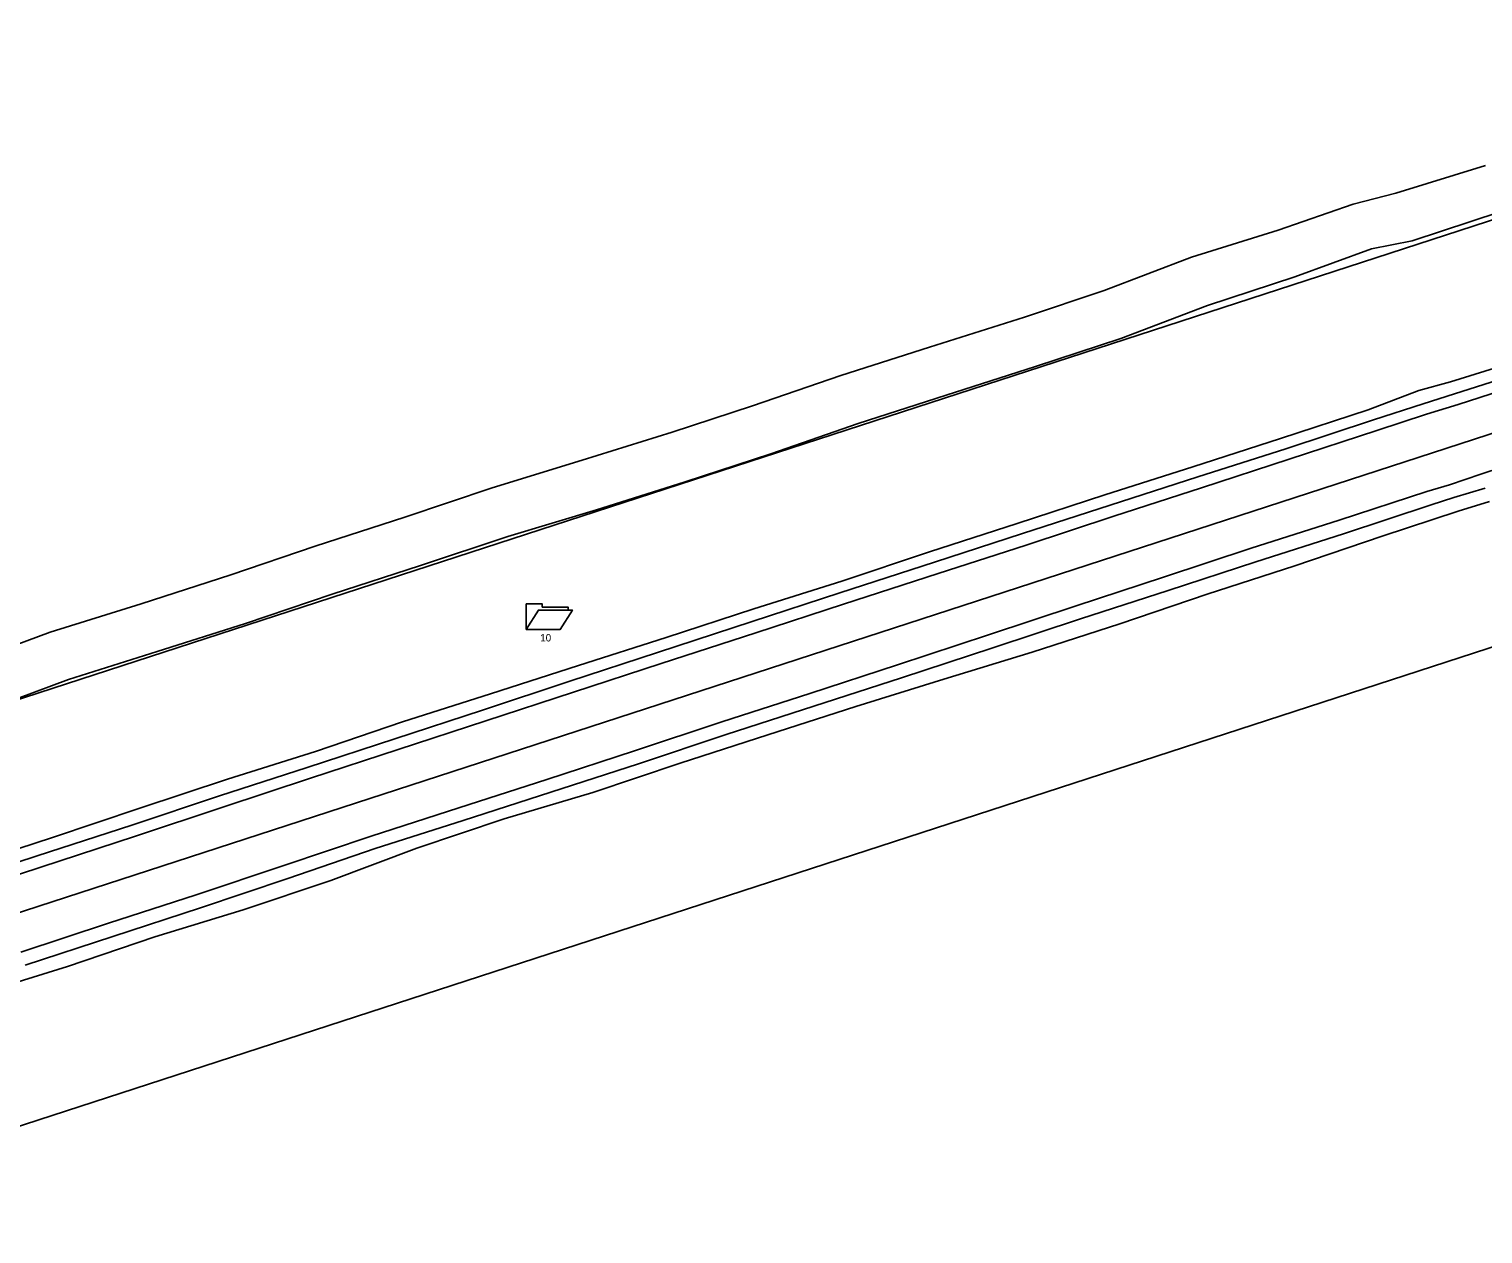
# Model space of a CAD drawing. Extents: x 1713040 to 1720428, y 375934 to 378258.
# Drawn here: x 1717153.3 to 1717547.4, y 376588.5 to 376914.9 of the extents above; entities that cross this region are included whole.
import ezdxf

# ---------------------------------------------------------------- set-up
doc = ezdxf.new("R2010")
doc.units = 0
for name, color, linetype in [('S_EDGE_PAVEMENT', 7, 'Continuous'), ('S_EXIST_ROW', 7, 'Continuous'), ('S_EXISTING_ALIGNMENT', 7, 'Continuous'), ('S_GRAVEL_ROAD', 7, 'Continuous'), ('S_SHOULDER', 7, 'Continuous'), ('S_TRAILS', 7, 'Continuous'), ('Scan Positions', 7, 'Continuous')]:
    doc.layers.add(name, color=color, linetype=linetype)

msp = doc.modelspace()

# ---------------------------------------------------------------- linework, layer by layer
at = {"layer": 'S_EDGE_PAVEMENT'}
for points in [[(1717540.67, 376813.18), (1717564.46, 376820.87)], [(1717132.73, 376680.11), (1717156.52, 376687.8), (1717182.16, 376696.27), (1717205.89, 376704.11), (1717229.64, 376711.93), (1717253.38, 376719.77), (1717277.15, 376727.51), (1717300.9, 376735.31), (1717324.68, 376743.05), (1717350.36, 376751.37), (1717374.14, 376759.09), (1717399.8, 376767.45), (1717423.59, 376775.14), (1717447.35, 376782.92), (1717471.12, 376790.67), (1717494.9, 376798.36), (1717518.67, 376806.13), (1717532.15, 376810.61), (1717540.67, 376813.18)], [(1717546.81, 376794.35), (1717570.57, 376802.13)], [(1717151.12, 376664.84), (1717174.88, 376672.63), (1717198.65, 376680.37), (1717222.35, 376688.33), (1717246.05, 376696.26), (1717269.86, 376703.91), (1717293.64, 376711.63), (1717317.41, 376719.36), (1717341.15, 376727.19), (1717364.93, 376734.9), (1717388.71, 376742.67), (1717413.42, 376750.76), (1717437.14, 376758.65), (1717460.88, 376766.47), (1717484.63, 376774.28), (1717508.46, 376781.87), (1717532.22, 376789.62), (1717538.4, 376791.49), (1717546.81, 376794.35)]]:
    msp.add_lwpolyline(points, dxfattribs=at)
at = {"layer": 'S_EXIST_ROW'}
for p, q in [((1716721.79, 376593.89), (1719194.33, 377397.97)), ((1716721.79, 376593.89), (1719194.33, 377397.97)), ((1716397, 376372.59), (1719323.44, 377324.29)), ((1716397, 376372.59), (1719321.66, 377323.71))]:
    msp.add_line(p, q, dxfattribs=at)
at = {"layer": 'S_EXISTING_ALIGNMENT'}
msp.add_line((1716440.47, 376444.57), (1719554.59, 377457.3), dxfattribs=at)
at = {"layer": 'S_GRAVEL_ROAD'}
for points in [[(1717538.66, 376819.34), (1717562.53, 376826.79)], [(1717135.87, 376688.14), (1717159.66, 376695.85), (1717183.33, 376703.83), (1717207.1, 376711.65), (1717230.93, 376719.19), (1717254.6, 376727.25), (1717278.41, 376734.83), (1717302.22, 376742.5), (1717326.05, 376750.06), (1717349.8, 376757.84), (1717373.67, 376765.32), (1717397.38, 376773.26), (1717421.16, 376780.97), (1717444.91, 376788.76), (1717468.75, 376796.31), (1717492.55, 376803.99), (1717516.29, 376811.77), (1717530.05, 376817.04), (1717538.66, 376819.34)], [(1717139.84, 376653.51), (1717163.76, 376660.89), (1717187.4, 376668.99), (1717211.37, 376676.29), (1717235.09, 376684.21), (1717258.44, 376693.01), (1717282.15, 376700.97), (1717306.12, 376708.09), (1717329.86, 376716.04), (1717353.61, 376723.71), (1717377.41, 376731.4), (1717401.32, 376738.76), (1717425.24, 376746.08), (1717449, 376753.77), (1717472.7, 376761.78), (1717496.45, 376769.48), (1717520.14, 376777.55), (1717540.75, 376784.33), (1717549.21, 376786.96)]]:
    msp.add_lwpolyline(points, dxfattribs=at)
at = {"layer": 'S_SHOULDER'}
for points in [[(1717539.71, 376816.11), (1717563.53, 376823.73)], [(1717131.75, 376683.11), (1717155.51, 376690.88), (1717181.18, 376699.25), (1717204.91, 376707.13), (1717228.68, 376714.88), (1717252.44, 376722.65), (1717276.21, 376730.38), (1717299.96, 376738.22), (1717323.71, 376745.99), (1717349.38, 376754.38), (1717373.13, 376762.18), (1717398.8, 376770.51), (1717422.58, 376778.23), (1717446.36, 376785.94), (1717470.15, 376793.62), (1717493.96, 376801.24), (1717517.72, 376809.03), (1717531.23, 376813.41), (1717539.71, 376816.11)], [(1717152.27, 376661.32), (1717176.03, 376669.09), (1717199.81, 376676.8), (1717223.49, 376684.81), (1717247.17, 376692.86), (1717270.97, 376700.49), (1717294.77, 376708.16), (1717318.55, 376715.86), (1717342.27, 376723.77), (1717366.06, 376731.45), (1717389.85, 376739.17), (1717414.56, 376747.26), (1717438.3, 376755.1), (1717462.08, 376762.81), (1717485.84, 376770.6), (1717509.65, 376778.21), (1717533.41, 376785.99), (1717539.54, 376788.01), (1717548.04, 376790.57)]]:
    msp.add_lwpolyline(points, dxfattribs=at)
at = {"layer": 'S_TRAILS'}
for points in [[(1717523.84, 376870.52), (1717548.15, 376877.97)], [(1717136.82, 376743.33), (1717159.07, 376751.54), (1717183.74, 376759.16), (1717208.04, 376767.05), (1717230.88, 376774.82), (1717255.21, 376782.69), (1717278.83, 376790.65), (1717303.24, 376798.16), (1717327.64, 376805.7), (1717349.47, 376812.85), (1717373.4, 376821.04), (1717397.37, 376828.73), (1717423.13, 376836.91), (1717444.74, 376844.1), (1717468.4, 376853.12), (1717491.95, 376860.46), (1717512.23, 376867.48), (1717523.84, 376870.52)], [(1717528.27, 376857.61), (1717552.13, 376865.42)], [(1717140.9, 376730.13), (1717164.03, 376738.7), (1717188.08, 376746.26), (1717212.02, 376753.88), (1717235.49, 376761.85), (1717259.4, 376769.58), (1717283.11, 376777.46), (1717307.17, 376784.7), (1717331.16, 376792.24), (1717354.38, 376799.83), (1717378.07, 376808.04), (1717401.91, 376815.74), (1717426.18, 376823.49), (1717449.31, 376831.12), (1717472.77, 376840.07), (1717496.44, 376847.77), (1717517.19, 376855.41), (1717528.27, 376857.61)]]:
    msp.add_lwpolyline(points, dxfattribs=at)
at = {"layer": 'Scan Positions'}
for points in [[(1717288.09, 376752.27), (1717288.09, 376759.19), (1717292.42, 376759.19), (1717292.42, 376758.3), (1717299.43, 376758.3), (1717299.43, 376757.49), (1717291.39, 376757.49)], [(1717288.09, 376752.27), (1717297.34, 376752.27), (1717300.63, 376757.49), (1717291.39, 376757.49)]]:
    msp.add_lwpolyline(points, close=True, dxfattribs=at)

# ---------------------------------------------------------------- texts
msp.add_text('10', height=2, dxfattribs=at).set_placement((1717291.88, 376749))

doc.saveas('drawing.dxf')
